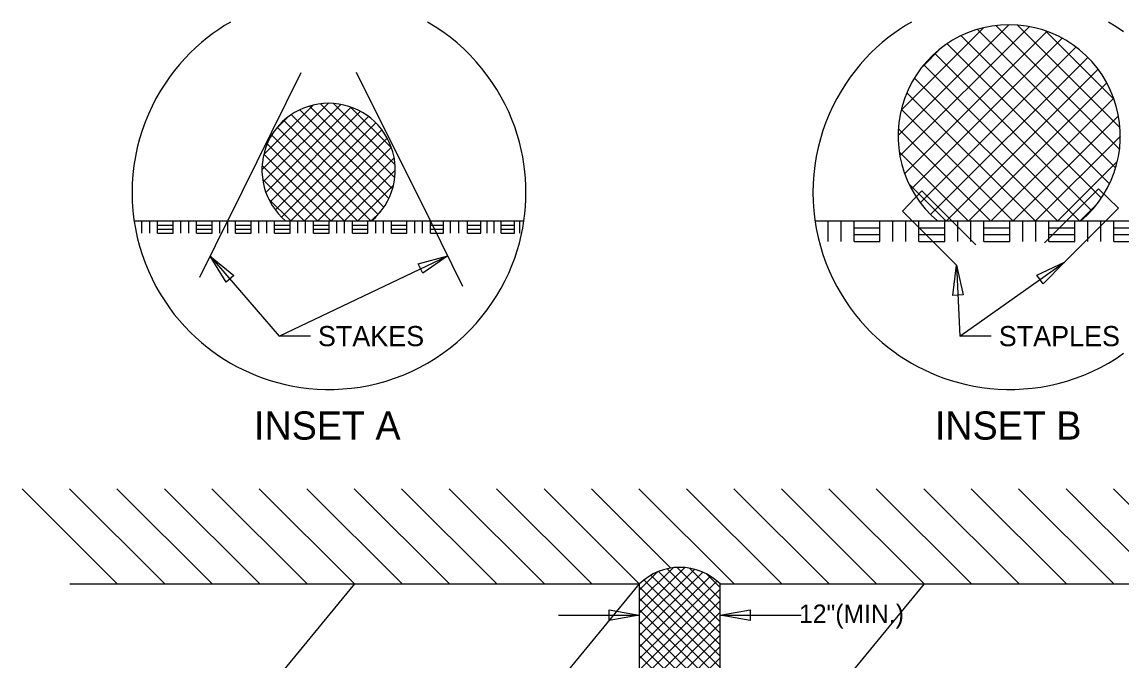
# Model space of a CAD drawing. Extents: x 8096 to 9796, y 9620 to 10720.
# Drawn here: x 9153.8 to 9561.9, y 9983.4 to 10220.5 of the extents above; entities that cross this region are included whole.
import ezdxf

# ---------------------------------------------------------------- set-up
doc = ezdxf.new("R2010")
doc.units = 0
for name, color, linetype in [('Default', 7, 'Continuous'), ('Old_Level_1', 7, 'Continuous'), ('Old_Level_2', 7, 'Continuous')]:
    doc.layers.add(name, color=color, linetype=linetype)

msp = doc.modelspace()

# ---------------------------------------------------------------- linework, layer by layer
at = {"layer": 'Default'}
for p, q in [((9478.89, 10178.37), (9519.93, 10219.41)), ((9479.55, 10170.76), (9527.55, 10218.76)), ((9480, 10187.75), (9510.58, 10218.33)), ((9481.31, 10164.26), (9534.02, 10216.96)), ((9502.28, 10215.4), (9557.25, 10160.44)), ((9508.28, 10217.67), (9559.54, 10166.41)), ((9515.1, 10219.13), (9560.98, 10173.24)), ((9523.16, 10219.33), (9561.15, 10181.34)), ((9533.67, 10217.08), (9558.99, 10191.77)), ((9483.86, 10158.54), (9539.76, 10214.43)), ((9497.05, 10212.37), (9554.22, 10155.19)), ((9487.11, 10153.52), (9544.77, 10211.18)), ((9487.76, 10203.77), (9494.7, 10210.72)), ((9490.93, 10149.07), (9549.19, 10207.33)), ((9492.42, 10208.73), (9550.62, 10150.53)), ((9488.34, 10204.55), (9546.21, 10146.67)), ((9484.93, 10199.69), (9537.94, 10146.67)), ((9496.8, 10146.67), (9553.07, 10202.94)), ((9505.07, 10146.67), (9556.27, 10197.87)), ((9482.12, 10194.23), (9529.68, 10146.67)), ((9513.34, 10146.67), (9558.83, 10192.17)), ((9242.85, 10165.69), (9267.48, 10190.32)), ((9243.25, 10161.12), (9272.05, 10189.92)), ((9243.52, 10171.32), (9261.87, 10189.67)), ((9244.31, 10157.22), (9275.93, 10188.84)), ((9245.84, 10153.79), (9279.37, 10187.33)), ((9256.89, 10187.91), (9289.87, 10154.93)), ((9260.49, 10189.27), (9291.24, 10158.52)), ((9264.58, 10190.14), (9292.11, 10162.61)), ((9269.42, 10190.26), (9292.21, 10167.47)), ((9275.72, 10188.92), (9290.91, 10173.73)), ((9480.06, 10188.02), (9521.41, 10146.67)), ((9247.79, 10150.78), (9282.38, 10185.38)), ((9248.18, 10180.93), (9252.34, 10185.1)), ((9250.08, 10148.11), (9285.04, 10183.07)), ((9250.97, 10183.91), (9285.89, 10148.99)), ((9253.75, 10186.09), (9288.05, 10151.79)), ((9521.6, 10146.67), (9560.59, 10185.65)), ((9248.52, 10181.4), (9283.25, 10146.67)), ((9253.6, 10146.67), (9287.36, 10180.43)), ((9478.94, 10180.87), (9513.14, 10146.67)), ((9244.79, 10175.21), (9273.32, 10146.67)), ((9246.48, 10178.48), (9278.29, 10146.67)), ((9258.56, 10146.67), (9289.28, 10177.39)), ((9529.87, 10146.67), (9561.31, 10178.11)), ((9243.56, 10171.48), (9268.36, 10146.67)), ((9263.52, 10146.67), (9290.82, 10173.97)), ((9479.29, 10172.25), (9504.87, 10146.67)), ((9242.88, 10167.19), (9263.4, 10146.67)), ((9268.48, 10146.67), (9291.87, 10170.06)), ((9538.14, 10146.67), (9560.16, 10168.69)), ((9273.44, 10146.67), (9292.3, 10165.53)), ((9243.1, 10162.02), (9258.44, 10146.67)), ((9278.4, 10146.67), (9291.62, 10159.89)), ((9482.98, 10160.3), (9496.6, 10146.67)), ((9533.14, 10138.51), (9553.18, 10158.55)), ((9553.18, 10158.55), (9560.65, 10151.36)), ((9245.31, 10154.85), (9253.48, 10146.67)), ((9480.51, 10150.3), (9487.71, 10157.78)), ((9487.71, 10157.78), (9507.74, 10137.74)), ((9283.36, 10146.67), (9286.91, 10150.22)), ((9500.55, 10130.27), (9480.51, 10150.3)), ((9560.65, 10151.36), (9540.62, 10131.32)), ((9546.41, 10146.67), (9552.32, 10152.59)), ((9189.15, 10011.98), (9153.8, 10047.33)), ((9206.76, 10011.98), (9171.41, 10047.33)), ((9224.37, 10011.98), (9189.01, 10047.33)), ((9241.98, 10011.98), (9206.62, 10047.33)), ((9259.59, 10011.98), (9224.23, 10047.33)), ((9277.19, 10011.98), (9241.84, 10047.33)), ((9294.8, 10011.98), (9259.45, 10047.33)), ((9312.41, 10011.98), (9277.05, 10047.33)), ((9330.02, 10011.98), (9294.66, 10047.33)), ((9347.63, 10011.98), (9312.27, 10047.33)), ((9365.23, 10011.98), (9329.88, 10047.33)), ((9382.84, 10011.98), (9347.49, 10047.33)), ((9394.56, 10017.86), (9365.1, 10047.33)), ((9418.06, 10011.98), (9382.7, 10047.33)), ((9435.67, 10011.98), (9400.31, 10047.33)), ((9453.28, 10011.98), (9417.92, 10047.33)), ((9470.88, 10011.98), (9435.53, 10047.33)), ((9488.49, 10011.98), (9453.14, 10047.33)), ((9506.1, 10011.98), (9470.75, 10047.33)), ((9523.71, 10011.98), (9488.35, 10047.33)), ((9541.32, 10011.98), (9505.96, 10047.33)), ((9558.93, 10011.98), (9523.57, 10047.33)), ((9576.53, 10011.98), (9541.18, 10047.33)), ((9594.14, 10011.98), (9558.79, 10047.33)), ((9382.84, 10001.2), (9399.66, 10018.01)), ((9382.84, 10005.44), (9395.34, 10017.94)), ((9382.84, 9996.96), (9403.29, 10017.4)), ((9382.84, 10009.69), (9389.63, 10016.47)), ((9382.84, 9992.71), (9406.42, 10016.29)), ((9389.93, 10016.59), (9412.86, 9993.66)), ((9393.19, 10017.57), (9412.86, 9997.91)), ((9396.93, 10018.08), (9412.86, 10002.15)), ((9401.46, 10017.79), (9412.86, 10006.39)), ((9407.91, 10015.58), (9412.86, 10010.63)), ((9382.84, 9988.47), (9409.22, 10014.84)), ((9382.84, 9984.23), (9411.65, 10013.04)), ((9382.84, 10011.98), (9382.84, 9754.98)), ((9384.57, 10013.47), (9412.86, 9985.18)), ((9387.09, 10015.19), (9412.86, 9989.42)), ((9412.86, 9754.98), (9412.86, 10011.98)), ((9382.84, 10010.95), (9412.86, 9980.94)), ((9382.84, 9979.99), (9412.86, 10010)), ((9382.84, 10006.71), (9412.86, 9976.69)), ((9382.84, 9975.74), (9412.86, 10005.76)), ((9382.84, 10002.46), (9412.86, 9972.45)), ((9382.84, 9971.5), (9412.86, 10001.51)), ((9382.84, 9998.22), (9412.86, 9968.21)), ((9382.84, 9967.26), (9412.86, 9997.27)), ((9382.84, 9993.98), (9412.86, 9963.97)), ((9382.84, 9963.02), (9412.86, 9993.03)), ((9382.84, 9989.73), (9412.86, 9959.72)), ((9382.84, 9958.77), (9412.86, 9988.79)), ((9382.84, 9985.49), (9412.86, 9955.48)), ((9382.84, 9954.53), (9412.86, 9984.54))]:
    msp.add_line(p, q, dxfattribs=at)
for points in [[(9231.18, 10220.47), (9228.99, 10219.15)], [(9307.12, 10218.72), (9304.24, 10220.47)], [(9483.79, 10220.47), (9481.6, 10219.15)], [(9559.73, 10218.72), (9556.85, 10220.47)], [(9224.63, 10216.21), (9222.47, 10214.57)], [(9226.8, 10217.73), (9224.63, 10216.21)], [(9228.99, 10219.15), (9226.8, 10217.73)], [(9309.92, 10216.83), (9307.12, 10218.72)], [(9312.62, 10214.83), (9309.92, 10216.83)], [(9477.24, 10216.21), (9475.09, 10214.57)], [(9479.42, 10217.73), (9477.24, 10216.21)], [(9481.6, 10219.15), (9479.42, 10217.73)], [(9562.53, 10216.83), (9559.73, 10218.72)], [(9220.34, 10212.82), (9218.24, 10210.96)], [(9222.47, 10214.57), (9220.34, 10212.82)], [(9315.21, 10212.71), (9312.62, 10214.83)], [(9317.7, 10210.48), (9315.21, 10212.71)], [(9472.95, 10212.82), (9470.85, 10210.96)], [(9475.09, 10214.57), (9472.95, 10212.82)], [(9216.18, 10208.99), (9214.17, 10206.9)], [(9218.24, 10210.96), (9216.18, 10208.99)], [(9320.07, 10208.15), (9317.7, 10210.48)], [(9322.32, 10205.74), (9320.07, 10208.15)], [(9468.79, 10208.99), (9466.78, 10206.9)], [(9470.85, 10210.96), (9468.79, 10208.99)], [(9212.2, 10204.71), (9210.31, 10202.39)], [(9214.17, 10206.9), (9212.2, 10204.71)], [(9324.44, 10203.24), (9322.32, 10205.74)], [(9326.43, 10200.67), (9324.44, 10203.24)], [(9464.82, 10204.71), (9462.92, 10202.39)], [(9466.78, 10206.9), (9464.82, 10204.71)], [(9208.48, 10199.97), (9206.73, 10197.44)], [(9210.31, 10202.39), (9208.48, 10199.97)], [(9328.29, 10198.05), (9326.43, 10200.67)], [(9461.09, 10199.97), (9459.34, 10197.44)], [(9462.92, 10202.39), (9461.09, 10199.97)], [(9206.73, 10197.44), (9205.07, 10194.81)], [(9330.01, 10195.37), (9328.29, 10198.05)], [(9331.6, 10192.64), (9330.01, 10195.37)], [(9459.34, 10197.44), (9457.68, 10194.81)], [(9203.51, 10192.07), (9202.05, 10189.24)], [(9205.07, 10194.81), (9203.51, 10192.07)], [(9333.05, 10189.89), (9331.6, 10192.64)], [(9456.12, 10192.07), (9454.66, 10189.24)], [(9457.68, 10194.81), (9456.12, 10192.07)], [(9202.05, 10189.24), (9200.7, 10186.31)], [(9334.37, 10187.11), (9333.05, 10189.89)], [(9335.55, 10184.32), (9334.37, 10187.11)], [(9454.66, 10189.24), (9453.31, 10186.31)], [(9199.47, 10183.3), (9198.37, 10180.22)], [(9200.7, 10186.31), (9199.47, 10183.3)], [(9336.6, 10181.52), (9335.55, 10184.32)], [(9452.08, 10183.3), (9450.98, 10180.22)], [(9453.31, 10186.31), (9452.08, 10183.3)], [(9198.37, 10180.22), (9197.4, 10177.07)], [(9337.53, 10178.72), (9336.6, 10181.52)], [(9338.33, 10175.93), (9337.53, 10178.72)], [(9450.98, 10180.22), (9450.01, 10177.07)], [(9197.4, 10177.07), (9196.57, 10173.85)], [(9339.01, 10173.16), (9338.33, 10175.93)], [(9450.01, 10177.07), (9449.18, 10173.85)], [(9195.89, 10170.58), (9195.35, 10167.28)], [(9196.57, 10173.85), (9195.89, 10170.58)], [(9339.57, 10170.41), (9339.01, 10173.16)], [(9448.5, 10170.58), (9447.96, 10167.28)], [(9449.18, 10173.85), (9448.5, 10170.58)], [(9195.35, 10167.28), (9194.96, 10163.93)], [(9340.01, 10167.69), (9339.57, 10170.41)], [(9340.35, 10165), (9340.01, 10167.69)], [(9447.96, 10167.28), (9447.57, 10163.93)], [(9194.96, 10163.93), (9194.73, 10160.57)], [(9340.59, 10162.36), (9340.35, 10165)], [(9340.73, 10159.76), (9340.59, 10162.36)], [(9447.57, 10163.93), (9447.34, 10160.57)], [(9194.73, 10160.57), (9194.65, 10157.2)], [(9340.77, 10157.2), (9340.73, 10159.76)], [(9447.34, 10160.57), (9447.26, 10157.2)], [(9194.65, 10157.2), (9194.73, 10153.83)], [(9340.59, 10152.04), (9340.73, 10154.64)], [(9340.73, 10154.64), (9340.77, 10157.2)], [(9447.26, 10157.2), (9447.34, 10153.83)], [(9194.73, 10153.83), (9194.96, 10150.47)], [(9194.96, 10150.47), (9195.35, 10147.12)], [(9340.35, 10149.4), (9340.59, 10152.04)], [(9447.34, 10153.83), (9447.57, 10150.47)], [(9447.57, 10150.47), (9447.96, 10147.12)], [(9195.35, 10147.12), (9195.89, 10143.82)], [(9339.57, 10143.99), (9340.01, 10146.71)], [(9340.01, 10146.71), (9340.35, 10149.4)], [(9447.96, 10147.12), (9448.5, 10143.82)], [(9195.89, 10143.82), (9196.57, 10140.55)], [(9339.01, 10141.24), (9339.57, 10143.99)], [(9448.5, 10143.82), (9449.18, 10140.55)], [(9196.57, 10140.55), (9197.4, 10137.33)], [(9337.53, 10135.68), (9338.33, 10138.47)], [(9338.33, 10138.47), (9339.01, 10141.24)], [(9449.18, 10140.55), (9450.01, 10137.33)], [(9197.4, 10137.33), (9198.37, 10134.18)], [(9198.37, 10134.18), (9199.47, 10131.1)], [(9336.6, 10132.88), (9337.53, 10135.68)], [(9450.01, 10137.33), (9450.98, 10134.18)], [(9450.98, 10134.18), (9452.08, 10131.1)], [(9199.47, 10131.1), (9200.7, 10128.09)], [(9334.37, 10127.29), (9335.55, 10130.08)], [(9335.55, 10130.08), (9336.6, 10132.88)], [(9452.08, 10131.1), (9453.31, 10128.09)], [(9200.7, 10128.09), (9202.05, 10125.16)], [(9333.05, 10124.51), (9334.37, 10127.29)], [(9453.31, 10128.09), (9454.66, 10125.16)], [(9202.05, 10125.16), (9203.51, 10122.33)], [(9203.51, 10122.33), (9205.07, 10119.59)], [(9330.01, 10119.03), (9331.6, 10121.76)], [(9331.6, 10121.76), (9333.05, 10124.51)], [(9454.66, 10125.16), (9456.12, 10122.33)], [(9456.12, 10122.33), (9457.68, 10119.59)], [(9205.07, 10119.59), (9206.73, 10116.96)], [(9328.29, 10116.35), (9330.01, 10119.03)], [(9457.68, 10119.59), (9459.34, 10116.96)], [(9206.73, 10116.96), (9208.48, 10114.43)], [(9208.48, 10114.43), (9210.31, 10112.01)], [(9324.44, 10111.16), (9326.43, 10113.73)], [(9326.43, 10113.73), (9328.29, 10116.35)], [(9459.34, 10116.96), (9461.09, 10114.43)], [(9461.09, 10114.43), (9462.92, 10112.01)], [(9210.31, 10112.01), (9212.2, 10109.69)], [(9212.2, 10109.69), (9214.17, 10107.5)], [(9322.32, 10108.66), (9324.44, 10111.16)], [(9462.92, 10112.01), (9464.82, 10109.69)], [(9464.82, 10109.69), (9466.78, 10107.5)], [(9214.17, 10107.5), (9216.18, 10105.41)], [(9216.18, 10105.41), (9218.24, 10103.44)], [(9317.7, 10103.92), (9320.07, 10106.25)], [(9320.07, 10106.25), (9322.32, 10108.66)], [(9466.78, 10107.5), (9468.79, 10105.41)], [(9468.79, 10105.41), (9470.85, 10103.44)], [(9218.24, 10103.44), (9220.34, 10101.58)], [(9220.34, 10101.58), (9222.47, 10099.83)], [(9312.62, 10099.57), (9315.21, 10101.69)], [(9315.21, 10101.69), (9317.7, 10103.92)], [(9470.85, 10103.44), (9472.95, 10101.58)], [(9472.95, 10101.58), (9475.09, 10099.83)], [(9222.47, 10099.83), (9224.63, 10098.19)], [(9224.63, 10098.19), (9226.8, 10096.67)], [(9307.12, 10095.68), (9309.92, 10097.57)], [(9309.92, 10097.57), (9312.62, 10099.57)], [(9475.09, 10099.83), (9477.24, 10098.19)], [(9477.24, 10098.19), (9479.42, 10096.67)], [(9559.73, 10095.68), (9562.53, 10097.57)], [(9226.8, 10096.67), (9228.99, 10095.25)], [(9228.99, 10095.25), (9231.18, 10093.93)], [(9231.18, 10093.93), (9233.42, 10092.69)], [(9301.28, 10092.31), (9304.24, 10093.93)], [(9304.24, 10093.93), (9307.12, 10095.68)], [(9479.42, 10096.67), (9481.6, 10095.25)], [(9481.6, 10095.25), (9483.79, 10093.93)], [(9483.79, 10093.93), (9486.03, 10092.69)], [(9553.89, 10092.31), (9556.85, 10093.93)], [(9556.85, 10093.93), (9559.73, 10095.68)], [(9233.42, 10092.69), (9235.74, 10091.51)], [(9235.74, 10091.51), (9238.15, 10090.39)], [(9238.15, 10090.39), (9240.64, 10089.34)], [(9240.64, 10089.34), (9243.22, 10088.37)], [(9292.03, 10088.31), (9295.17, 10089.5)], [(9295.17, 10089.5), (9298.25, 10090.83)], [(9298.25, 10090.83), (9301.28, 10092.31)], [(9486.03, 10092.69), (9488.35, 10091.51)], [(9488.35, 10091.51), (9490.76, 10090.39)], [(9490.76, 10090.39), (9493.26, 10089.34)], [(9493.26, 10089.34), (9495.83, 10088.37)], [(9544.64, 10088.31), (9547.78, 10089.5)], [(9547.78, 10089.5), (9550.86, 10090.83)], [(9550.86, 10090.83), (9553.89, 10092.31)], [(9243.22, 10088.37), (9245.88, 10087.48)], [(9245.88, 10087.48), (9248.62, 10086.68)], [(9248.62, 10086.68), (9251.44, 10085.98)], [(9251.44, 10085.98), (9254.32, 10085.38)], [(9254.32, 10085.38), (9257.27, 10084.89)], [(9257.27, 10084.89), (9260.28, 10084.52)], [(9276, 10084.61), (9279.22, 10085.05)], [(9279.22, 10085.05), (9282.44, 10085.64)], [(9282.44, 10085.64), (9285.66, 10086.38)], [(9285.66, 10086.38), (9288.86, 10087.27)], [(9288.86, 10087.27), (9292.03, 10088.31)], [(9495.83, 10088.37), (9498.5, 10087.48)], [(9498.5, 10087.48), (9501.23, 10086.68)], [(9501.23, 10086.68), (9504.05, 10085.98)], [(9504.05, 10085.98), (9506.93, 10085.38)], [(9506.93, 10085.38), (9509.88, 10084.89)], [(9509.88, 10084.89), (9512.9, 10084.52)], [(9528.61, 10084.61), (9531.83, 10085.05)], [(9531.83, 10085.05), (9535.05, 10085.64)], [(9535.05, 10085.64), (9538.27, 10086.38)], [(9538.27, 10086.38), (9541.47, 10087.27)], [(9541.47, 10087.27), (9544.64, 10088.31)], [(9260.28, 10084.52), (9263.35, 10084.27)], [(9263.35, 10084.27), (9266.46, 10084.15)], [(9266.46, 10084.15), (9269.61, 10084.17)], [(9269.61, 10084.17), (9272.8, 10084.32)], [(9272.8, 10084.32), (9276, 10084.61)], [(9512.9, 10084.52), (9515.96, 10084.27)], [(9515.96, 10084.27), (9519.07, 10084.15)], [(9519.07, 10084.15), (9522.22, 10084.17)], [(9522.22, 10084.17), (9525.41, 10084.32)], [(9525.41, 10084.32), (9528.61, 10084.61)], [(9277.19, 10011.98), (9171.54, 9883.48), (9277.19, 9754.98)], [(9382.84, 10011.98), (9277.19, 9883.48), (9382.84, 9754.98)], [(9488.49, 10011.98), (9428.12, 9938.55)]]:
    msp.add_lwpolyline(points, dxfattribs=at)
for centre, radius, start, end in [((9520.07, 10178.21), 41.24, 310.1144, 229.8856), ((9267.56, 10165.6), 24.74, 310.1144, 229.8856), ((9397.85, 9996.71), 21.41, 45.4932, 134.5068)]:
    msp.add_arc(centre, radius, start, end, dxfattribs=at)
at = {"layer": 'Old_Level_1'}
for p, q in [((9230.12, 10146.67), (9257.4, 10201.75)), ((9305.31, 10146.67), (9277.9, 10201.75)), ((9195.42, 10146.67), (9340.01, 10146.67)), ((9198.31, 10142.09), (9198.31, 10146.67)), ((9201.21, 10142.09), (9201.21, 10146.67)), ((9204.1, 10142.09), (9204.1, 10146.67)), ((9209.88, 10142.09), (9209.88, 10146.67)), ((9212.77, 10142.09), (9212.77, 10146.67)), ((9215.66, 10142.09), (9215.66, 10146.67)), ((9218.56, 10142.09), (9218.56, 10146.67)), ((9219.78, 10125.79), (9231.42, 10149.29)), ((9224.34, 10142.09), (9224.34, 10146.67)), ((9227.23, 10142.09), (9227.23, 10146.67)), ((9230.12, 10142.09), (9230.12, 10146.67)), ((9233.01, 10142.09), (9233.01, 10146.67)), ((9238.8, 10142.09), (9238.8, 10146.67)), ((9241.69, 10142.09), (9241.69, 10146.67)), ((9244.58, 10142.09), (9244.58, 10146.67)), ((9247.47, 10142.09), (9247.47, 10146.67)), ((9253.26, 10142.09), (9253.26, 10146.67)), ((9256.15, 10142.09), (9256.15, 10146.67)), ((9259.04, 10142.09), (9259.04, 10146.67)), ((9261.93, 10142.09), (9261.93, 10146.67)), ((9267.71, 10142.09), (9267.71, 10146.67)), ((9270.61, 10142.09), (9270.61, 10146.67)), ((9273.5, 10142.09), (9273.5, 10146.67)), ((9276.39, 10142.09), (9276.39, 10146.67)), ((9282.17, 10142.09), (9282.17, 10146.67)), ((9285.06, 10142.09), (9285.06, 10146.67)), ((9287.96, 10142.09), (9287.96, 10146.67)), ((9290.85, 10142.09), (9290.85, 10146.67)), ((9296.63, 10142.09), (9296.63, 10146.67)), ((9299.52, 10142.09), (9299.52, 10146.67)), ((9302.41, 10142.09), (9302.41, 10146.67)), ((9305.31, 10142.09), (9305.31, 10146.67)), ((9317.39, 10122.39), (9305.31, 10146.67)), ((9310.17, 10142.09), (9310.17, 10146.67)), ((9312.79, 10142.09), (9312.79, 10146.67)), ((9315.91, 10142.09), (9315.91, 10146.67)), ((9319.14, 10142.09), (9319.14, 10146.67)), ((9324, 10142.09), (9324, 10146.67)), ((9326.38, 10142.09), (9326.38, 10146.67)), ((9329.04, 10142.09), (9329.04, 10146.67)), ((9331.63, 10142.09), (9331.63, 10146.67)), ((9336.49, 10142.09), (9336.49, 10146.67)), ((9338.49, 10142.09), (9338.49, 10146.67)), ((9448.03, 10146.67), (9592.62, 10146.67)), ((9452.85, 10139.04), (9452.85, 10146.67)), ((9457.67, 10139.04), (9457.67, 10146.67)), ((9462.49, 10139.04), (9462.49, 10146.67)), ((9472.13, 10139.04), (9472.13, 10146.67)), ((9476.95, 10139.04), (9476.95, 10146.67)), ((9481.77, 10139.04), (9481.77, 10146.67)), ((9486.59, 10139.04), (9486.59, 10146.67)), ((9496.23, 10139.04), (9496.23, 10146.67)), ((9501.05, 10139.04), (9501.05, 10146.67)), ((9505.87, 10139.04), (9505.87, 10146.67)), ((9510.69, 10139.04), (9510.69, 10146.67)), ((9520.33, 10139.04), (9520.33, 10146.67)), ((9525.15, 10139.04), (9525.15, 10146.67)), ((9529.96, 10139.04), (9529.96, 10146.67)), ((9534.78, 10139.04), (9534.78, 10146.67)), ((9544.42, 10139.04), (9544.42, 10146.67)), ((9549.24, 10139.04), (9549.24, 10146.67)), ((9554.06, 10139.04), (9554.06, 10146.67)), ((9558.88, 10139.04), (9558.88, 10146.67)), ((9171.54, 10011.98), (9382.84, 10011.98)), ((9412.86, 10011.98), (9699.79, 10011.98)), ((9352.83, 10000.45), (9382.84, 10000.45)), ((9412.86, 10000.45), (9442.87, 10000.45))]:
    msp.add_line(p, q, dxfattribs=at)
for points in [[(9204.1, 10145.15), (9209.88, 10145.15)], [(9204.1, 10143.62), (9209.88, 10143.62)], [(9204.1, 10142.09), (9209.88, 10142.09)], [(9218.56, 10145.15), (9224.34, 10145.15)], [(9218.56, 10143.62), (9224.34, 10143.62)], [(9218.56, 10142.09), (9224.34, 10142.09)], [(9233.01, 10145.15), (9238.8, 10145.15)], [(9233.01, 10143.62), (9238.8, 10143.62)], [(9233.01, 10142.09), (9238.8, 10142.09)], [(9247.47, 10145.15), (9253.26, 10145.15)], [(9247.47, 10143.62), (9253.26, 10143.62)], [(9247.47, 10142.09), (9253.26, 10142.09)], [(9261.93, 10145.15), (9267.71, 10145.15)], [(9261.93, 10143.62), (9267.71, 10143.62)], [(9261.93, 10142.09), (9267.71, 10142.09)], [(9276.39, 10145.15), (9282.17, 10145.15)], [(9276.39, 10143.62), (9282.17, 10143.62)], [(9276.39, 10142.09), (9282.17, 10142.09)], [(9290.85, 10145.15), (9296.63, 10145.15)], [(9290.85, 10143.62), (9296.63, 10143.62)], [(9290.85, 10142.09), (9296.63, 10142.09)], [(9305.31, 10145.15), (9310.17, 10145.15)], [(9305.31, 10143.62), (9310.17, 10143.62)], [(9305.31, 10142.09), (9310.17, 10142.09)], [(9319.14, 10145.15), (9324, 10145.15)], [(9319.14, 10143.62), (9324, 10143.62)], [(9319.14, 10142.09), (9324, 10142.09)], [(9331.63, 10145.15), (9336.49, 10145.15)], [(9331.63, 10143.62), (9336.49, 10143.62)], [(9331.63, 10142.09), (9336.49, 10142.09)], [(9462.49, 10144.13), (9472.13, 10144.13)], [(9486.59, 10144.13), (9496.23, 10144.13)], [(9510.69, 10144.13), (9520.33, 10144.13)], [(9534.78, 10144.13), (9544.42, 10144.13)], [(9558.88, 10144.13), (9568.52, 10144.13)], [(9462.49, 10141.58), (9472.13, 10141.58)], [(9462.49, 10139.04), (9472.13, 10139.04)], [(9486.59, 10141.58), (9496.23, 10141.58)], [(9486.59, 10139.04), (9496.23, 10139.04)], [(9510.69, 10141.58), (9520.33, 10141.58)], [(9510.69, 10139.04), (9520.33, 10139.04)], [(9534.78, 10141.58), (9544.42, 10141.58)], [(9534.78, 10139.04), (9544.42, 10139.04)], [(9558.88, 10141.58), (9568.52, 10141.58)], [(9558.88, 10139.04), (9568.52, 10139.04)]]:
    msp.add_lwpolyline(points, dxfattribs=at)
at = {"layer": 'Old_Level_2'}
for p, q in [((9223.66, 10133.62), (9249.18, 10103.88)), ((9500.55, 10130.27), (9501.79, 10103.88))]:
    msp.add_line(p, q, dxfattribs=at)
for points in [[(9260.79, 10103.88), (9249.18, 10103.88), (9311.75, 10133.72)], [(9513.4, 10103.88), (9501.79, 10103.88), (9540.62, 10131.32)]]:
    msp.add_lwpolyline(points, dxfattribs=at)
for points in [[(9311.75, 10133.72), (9302.48, 10127.24), (9300.82, 10130.76)], [(9223.66, 10133.62), (9232.42, 10126.47), (9229.49, 10123.91)], [(9500.55, 10130.27), (9503.01, 10119.23), (9499.13, 10119.03)], [(9540.62, 10131.32), (9532.61, 10123.32), (9530.37, 10126.5)], [(9382.84, 10000.45), (9371.69, 9998.48), (9371.69, 10002.37)], [(9412.86, 10000.45), (9424.01, 10002.37), (9424.01, 9998.48)]]:
    msp.add_lwpolyline(points, close=True, dxfattribs=at)

# ---------------------------------------------------------------- texts
at = {"layer": 'Old_Level_1'}
for s, height, p in [('STAKES', 7.47, (9263.59, 10100.2)), ('STAPLES', 7.47, (9516.2, 10100.2)), ('INSET A', 10.454, (9239.88, 10065.53)), ('INSET B', 10.454, (9492.5, 10065.53)), ('12"(MIN.)', 6.859, (9442.09, 9997.49))]:
    msp.add_text(s, height=height, dxfattribs=at).set_placement(p)

doc.saveas('drawing.dxf')
